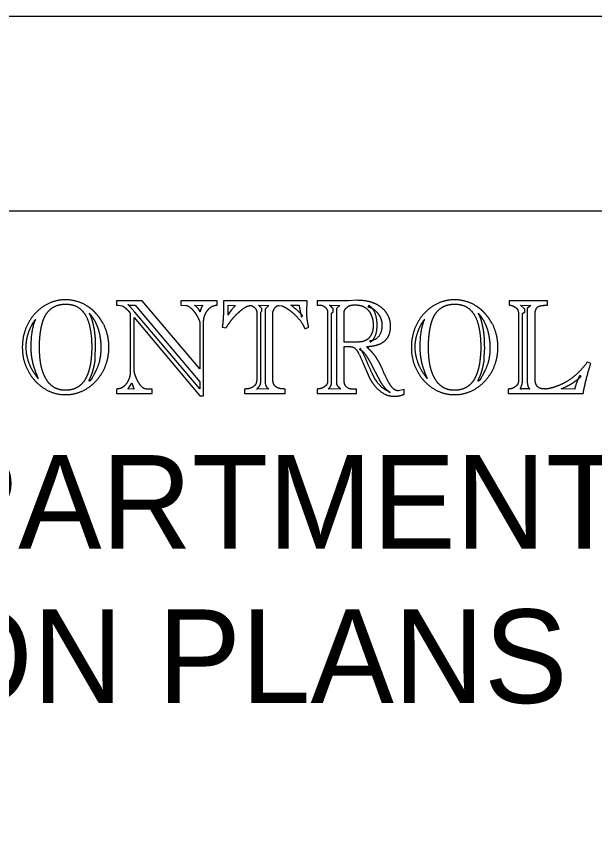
# Model space of a CAD drawing. Extents: x -0.96 to 2.36, y -0.12 to 0.92.
# Drawn here: x 0.6508 to 0.7127, y 0.8293 to 0.9167 of the extents above; entities that cross this region are included whole.
import ezdxf

# ---------------------------------------------------------------- set-up
doc = ezdxf.new("R2010")
doc.units = 0
for name, color, linetype in [('SHET_Border-Lines', 7, 'Continuous'), ('SHET_Border-Text', 7, 'Continuous'), ('SHET_Border-Text-Fully', 7, 'Continuous')]:
    doc.layers.add(name, color=color, linetype=linetype)

msp = doc.modelspace()

# ---------------------------------------------------------------- linework, layer by layer
at = {"layer": 'SHET_Border-Lines'}
for points in [[(0, 0), (1.416664, 0), (1.416664, 0.916665), (0, 0.916665)], [(0.041667, 0.020833), (1.395831, 0.020833), (1.395831, 0.895832), (0.041667, 0.895832)]]:
    msp.add_lwpolyline(points, close=True, dxfattribs=at)
at = {"layer": 'SHET_Border-Text-Fully'}
for p, q in [((0.656052, 0.886359), (0.656052, 0.886359)), ((0.697668, 0.886359), (0.697668, 0.886359)), ((0.654771, 0.885579), (0.654771, 0.885579)), ((0.662763, 0.885825), (0.662714, 0.885866)), ((0.662849, 0.885784), (0.663366, 0.885784)), ((0.669868, 0.88577), (0.670731, 0.885757)), ((0.678906, 0.885757), (0.679202, 0.885716)), ((0.680162, 0.885784), (0.681049, 0.885784)), ((0.687049, 0.885812), (0.687049, 0.885812)), ((0.688527, 0.88577), (0.688391, 0.88562)), ((0.696387, 0.885579), (0.696387, 0.885579)), ((0.658589, 0.884922), (0.658589, 0.884922)), ((0.66296, 0.884936), (0.662985, 0.878655)), ((0.670447, 0.885059), (0.670447, 0.885059)), ((0.676505, 0.885073), (0.676505, 0.877752)), ((0.678241, 0.877752), (0.678241, 0.884963)), ((0.681307, 0.884498), (0.681418, 0.884635)), ((0.684094, 0.885045), (0.684094, 0.877588)), ((0.700204, 0.884922), (0.700204, 0.884922)), ((0.704526, 0.884772), (0.704526, 0.87778)), ((0.704933, 0.87767), (0.704933, 0.884676)), ((0.706287, 0.877958), (0.706287, 0.884799)), ((0.672823, 0.883431), (0.673229, 0.883376)), ((0.681665, 0.883266), (0.682071, 0.883444)), ((0.688564, 0.881953), (0.688687, 0.88183)), ((0.659242, 0.880243), (0.659278, 0.881282)), ((0.687591, 0.881159), (0.687492, 0.88105)), ((0.700857, 0.880243), (0.700894, 0.881282)), ((0.687862, 0.879641), (0.688527, 0.878094)), ((0.71226, 0.879545), (0.711878, 0.879709)), ((0.711213, 0.878176), (0.711078, 0.878313)), ((0.653121, 0.877958), (0.653121, 0.877958)), ((0.662923, 0.877123), (0.663157, 0.877465)), ((0.694737, 0.877958), (0.694737, 0.877958)), ((0.676468, 0.876767), (0.676517, 0.876808)), ((0.677798, 0.876822), (0.676579, 0.876849)), ((0.705733, 0.876836), (0.704883, 0.876836))]:
    msp.add_line(p, q, dxfattribs=at)
for points in [[(0.67041, 0.883951), (0.67041, 0.878997), (0.664265, 0.886249), (0.661495, 0.886249), (0.661495, 0.885784), (0.661692, 0.885784), (0.66211, 0.885716)], [(0.672294, 0.885784), (0.672294, 0.886249), (0.668391, 0.886249), (0.668391, 0.885798), (0.66892, 0.885757)], [(0.681874, 0.885045), (0.681923, 0.886249), (0.672971, 0.886249)], [(0.687221, 0.886304), (0.68631, 0.886249), (0.682985, 0.886249), (0.682985, 0.885784), (0.683367, 0.885784)], [(0.707629, 0.885784), (0.707629, 0.886249), (0.703516, 0.886249), (0.703516, 0.885812)], [(0.663539, 0.885743), (0.663859, 0.885374), (0.67041, 0.877588), (0.67041, 0.876836), (0.663477, 0.885032), (0.662935, 0.885661)], [(0.676948, 0.877643), (0.676948, 0.885032), (0.677071, 0.885141), (0.677071, 0.885428), (0.676763, 0.885716), (0.676702, 0.885784), (0.677822, 0.885757), (0.677416, 0.885346), (0.677416, 0.877588)], [(0.684352, 0.885757), (0.684291, 0.885812), (0.684327, 0.885784), (0.685411, 0.885757), (0.685029, 0.885428), (0.685029, 0.877479)], [(0.6845, 0.877424), (0.6845, 0.884936), (0.684697, 0.885073), (0.684697, 0.885387)], [(0.705204, 0.885032), (0.705204, 0.885374), (0.704736, 0.885784), (0.705832, 0.885757), (0.705438, 0.885428), (0.705438, 0.87778)], [(0.663391, 0.878847), (0.663391, 0.884484), (0.670435, 0.87611), (0.670829, 0.87611), (0.670829, 0.884033)], [(0.68732, 0.881844), (0.685879, 0.881844), (0.685879, 0.884908), (0.685854, 0.884936)], [(0.685879, 0.877561), (0.685879, 0.881351), (0.686519, 0.881351)], [(0.688748, 0.87949), (0.689179, 0.878642), (0.689758, 0.877574)], [(0.661495, 0.876822), (0.661495, 0.876329), (0.665324, 0.876329), (0.665324, 0.876795), (0.664696, 0.876822)], [(0.663391, 0.876822), (0.662775, 0.876836), (0.662763, 0.876822)], [(0.675212, 0.876822), (0.675212, 0.876329), (0.679547, 0.876329), (0.679547, 0.876822)], [(0.682961, 0.876822), (0.682961, 0.876329), (0.687172, 0.876357), (0.687172, 0.876822), (0.686618, 0.876822)], [(0.685251, 0.877041), (0.68546, 0.876822), (0.684167, 0.876849), (0.684266, 0.876918)], [(0.692295, 0.876261), (0.692295, 0.876767), (0.691679, 0.87663)], [(0.703418, 0.876822), (0.703418, 0.876329), (0.711435, 0.876329)], [(0.710523, 0.876822), (0.709083, 0.876836), (0.709538, 0.877041)]]:
    msp.add_lwpolyline(points, dxfattribs=at)
msp.add_lwpolyline([(0.673438, 0.885784), (0.674214, 0.885757), (0.674079, 0.885606), (0.673783, 0.885264), (0.673537, 0.884895), (0.673438, 0.88473)], close=True, dxfattribs=at)
for points in [[(0.656052, 0.886359), (0.654784, 0.886359), (0.653725, 0.885675)], [(0.65838, 0.885688), (0.657296, 0.886359), (0.656052, 0.886359)], [(0.672971, 0.886249), (0.672971, 0.884293), (0.672823, 0.883431)], [(0.689222, 0.885921), (0.688416, 0.886304), (0.687221, 0.886304)], [(0.697668, 0.886359), (0.696399, 0.886359), (0.69534, 0.885675)], [(0.699995, 0.885688), (0.698911, 0.886359), (0.697668, 0.886359)], [(0.653725, 0.885675), (0.652666, 0.884991), (0.65205, 0.883828)], [(0.653922, 0.884717), (0.65423, 0.885264), (0.654771, 0.885579)], [(0.654771, 0.885579), (0.655326, 0.885894), (0.656077, 0.885894)], [(0.656077, 0.885894), (0.657099, 0.885894), (0.657708, 0.885326)], [(0.657708, 0.885326), (0.658318, 0.884758), (0.658589, 0.883718)], [(0.659322, 0.884888), (0.658897, 0.88536), (0.65838, 0.885688)], [(0.66211, 0.885716), (0.662221, 0.885688), (0.662406, 0.885524)], [(0.662406, 0.885524), (0.662578, 0.885401), (0.662646, 0.885326)], [(0.662646, 0.885326), (0.662714, 0.88525), (0.662812, 0.885155)], [(0.662714, 0.885866), (0.662726, 0.885866), (0.662849, 0.885784)], [(0.662935, 0.885661), (0.662886, 0.885716), (0.662763, 0.885825)], [(0.663366, 0.885784), (0.663502, 0.885784), (0.663539, 0.885743)], [(0.66892, 0.885757), (0.669191, 0.885757), (0.669548, 0.885401)], [(0.669548, 0.885401), (0.669905, 0.885045), (0.670158, 0.88458)], [(0.670447, 0.885059), (0.670312, 0.885456), (0.669868, 0.88577)], [(0.670731, 0.885757), (0.670521, 0.885483), (0.670447, 0.885059)], [(0.67102, 0.884847), (0.671211, 0.885264), (0.671531, 0.885524)], [(0.671531, 0.885524), (0.671851, 0.885784), (0.672294, 0.885784)], [(0.674565, 0.885004), (0.674793, 0.885209), (0.675039, 0.885401)], [(0.675039, 0.885401), (0.675544, 0.885757), (0.675889, 0.885757)], [(0.675889, 0.885757), (0.675914, 0.885743), (0.675957, 0.885736)], [(0.675957, 0.885736), (0.676, 0.885729), (0.676086, 0.885661)], [(0.676086, 0.885661), (0.676259, 0.885579), (0.676382, 0.885415)], [(0.676382, 0.885415), (0.676505, 0.88525), (0.676505, 0.885073)], [(0.678241, 0.884963), (0.678241, 0.885209), (0.678444, 0.885483)], [(0.678444, 0.885483), (0.678647, 0.885757), (0.678906, 0.885757)], [(0.679202, 0.885716), (0.679522, 0.885593), (0.679873, 0.885353)], [(0.679873, 0.885353), (0.680224, 0.885114), (0.680605, 0.884744)], [(0.680729, 0.885333), (0.680285, 0.885702), (0.680162, 0.885784)], [(0.681418, 0.884635), (0.681172, 0.884963), (0.680729, 0.885333)], [(0.681049, 0.885784), (0.681049, 0.885702), (0.68116, 0.885168)], [(0.68116, 0.885168), (0.681197, 0.884963), (0.681307, 0.884498)], [(0.683367, 0.885784), (0.683589, 0.885784), (0.683841, 0.885551)], [(0.683841, 0.885551), (0.684094, 0.885319), (0.684094, 0.885045)], [(0.684697, 0.885387), (0.684549, 0.885551), (0.684352, 0.885757)], [(0.685854, 0.884936), (0.685854, 0.885305), (0.686162, 0.885551)], [(0.686162, 0.885551), (0.686335, 0.885702), (0.686519, 0.885757)], [(0.686519, 0.885757), (0.686704, 0.885812), (0.687049, 0.885812)], [(0.687049, 0.885812), (0.687714, 0.885812), (0.688126, 0.885524)], [(0.688126, 0.885524), (0.688539, 0.885237), (0.688755, 0.884737)], [(0.688391, 0.88562), (0.68881, 0.885538), (0.689142, 0.885237)], [(0.689389, 0.88365), (0.689389, 0.885114), (0.688527, 0.88577)], [(0.689142, 0.885237), (0.689487, 0.884963), (0.689709, 0.884525)], [(0.690429, 0.884902), (0.690029, 0.885538), (0.689222, 0.885921)], [(0.69534, 0.885675), (0.694281, 0.884991), (0.693665, 0.883828)], [(0.695537, 0.884717), (0.695845, 0.885264), (0.696387, 0.885579)], [(0.696387, 0.885579), (0.696941, 0.885894), (0.697692, 0.885894)], [(0.697692, 0.885894), (0.698714, 0.885894), (0.699324, 0.885326)], [(0.699324, 0.885326), (0.699933, 0.884758), (0.700204, 0.883718)], [(0.700937, 0.884888), (0.700512, 0.88536), (0.699995, 0.885688)], [(0.703516, 0.885812), (0.704058, 0.885702), (0.704292, 0.885469)], [(0.704292, 0.885469), (0.704526, 0.885237), (0.704526, 0.884772)], [(0.706287, 0.884799), (0.706287, 0.885442), (0.706644, 0.885647)], [(0.706644, 0.885647), (0.706903, 0.885784), (0.707629, 0.885784)], [(0.652111, 0.882883), (0.652382, 0.883663), (0.652863, 0.884306)], [(0.652863, 0.884306), (0.652345, 0.883253), (0.652345, 0.88131)], [(0.653645, 0.884101), (0.653762, 0.884443), (0.653922, 0.884717)], [(0.658589, 0.884922), (0.658613, 0.884895), (0.65865, 0.884854)], [(0.658983, 0.883923), (0.658847, 0.884498), (0.658589, 0.884922)], [(0.65865, 0.884854), (0.659032, 0.884416), (0.659309, 0.883841)], [(0.660067, 0.883841), (0.659746, 0.884416), (0.659322, 0.884888)], [(0.662812, 0.885155), (0.66296, 0.884963), (0.66296, 0.884936)], [(0.670158, 0.88458), (0.67041, 0.884115), (0.67041, 0.883951)], [(0.670829, 0.884033), (0.670829, 0.884429), (0.67102, 0.884847)], [(0.673229, 0.883376), (0.673586, 0.883964), (0.674054, 0.884484)], [(0.674054, 0.884484), (0.674337, 0.884799), (0.674565, 0.885004)], [(0.680605, 0.884744), (0.68132, 0.884087), (0.681665, 0.883266)], [(0.681917, 0.884211), (0.681874, 0.884553), (0.681874, 0.885045)], [(0.688755, 0.884737), (0.68897, 0.884238), (0.68897, 0.883622)], [(0.689709, 0.884525), (0.689906, 0.884101), (0.689906, 0.883677)], [(0.690829, 0.883581), (0.690829, 0.884265), (0.690429, 0.884902)], [(0.693727, 0.882883), (0.693998, 0.883663), (0.694478, 0.884306)], [(0.694478, 0.884306), (0.693961, 0.883253), (0.693961, 0.88131)], [(0.69526, 0.884101), (0.695377, 0.884443), (0.695537, 0.884717)], [(0.700204, 0.884922), (0.700229, 0.884895), (0.700266, 0.884854)], [(0.700598, 0.883923), (0.700463, 0.884498), (0.700204, 0.884922)], [(0.700266, 0.884854), (0.700648, 0.884416), (0.700925, 0.883841)], [(0.701682, 0.883841), (0.701362, 0.884416), (0.700937, 0.884888)], [(0.704933, 0.884676), (0.704933, 0.884867), (0.704957, 0.884908)], [(0.704957, 0.884908), (0.704982, 0.884949), (0.705204, 0.885032)], [(0.65205, 0.883828), (0.651434, 0.882664), (0.651434, 0.881282)], [(0.653441, 0.883301), (0.653528, 0.883759), (0.653645, 0.884101)], [(0.658589, 0.883718), (0.65886, 0.882678), (0.65886, 0.88131)], [(0.659205, 0.882726), (0.659131, 0.883335), (0.658983, 0.883923)], [(0.659309, 0.883841), (0.659586, 0.883266), (0.65971, 0.882596)], [(0.660695, 0.881282), (0.660695, 0.882692), (0.660067, 0.883841)], [(0.682071, 0.883444), (0.68196, 0.883869), (0.681917, 0.884211)], [(0.689906, 0.883677), (0.689906, 0.882103), (0.688564, 0.881953)], [(0.688687, 0.88183), (0.689389, 0.882377), (0.689389, 0.88365)], [(0.68897, 0.883622), (0.68897, 0.883198), (0.688859, 0.882877)], [(0.690442, 0.88222), (0.690829, 0.882733), (0.690829, 0.883581)], [(0.693665, 0.883828), (0.69305, 0.882664), (0.69305, 0.881282)], [(0.695057, 0.883301), (0.695143, 0.883759), (0.69526, 0.884101)], [(0.700204, 0.883718), (0.700475, 0.882678), (0.700475, 0.88131)], [(0.70082, 0.882726), (0.700746, 0.883335), (0.700598, 0.883923)], [(0.700925, 0.883841), (0.701202, 0.883266), (0.701325, 0.882596)], [(0.70231, 0.881282), (0.70231, 0.882692), (0.701682, 0.883841)], [(0.651841, 0.881282), (0.651841, 0.88209), (0.652111, 0.882883)], [(0.653312, 0.88235), (0.653355, 0.882842), (0.653441, 0.883301)], [(0.659278, 0.881282), (0.659278, 0.882117), (0.659205, 0.882726)], [(0.65971, 0.882596), (0.659771, 0.882254), (0.659808, 0.881912)], [(0.688859, 0.882877), (0.688748, 0.882555), (0.688539, 0.882309)], [(0.693456, 0.881282), (0.693456, 0.88209), (0.693727, 0.882883)], [(0.694928, 0.88235), (0.694971, 0.882842), (0.695057, 0.883301)], [(0.700894, 0.881282), (0.700894, 0.882117), (0.70082, 0.882726)], [(0.701325, 0.882596), (0.701387, 0.882254), (0.701423, 0.881912)], [(0.653269, 0.881282), (0.653269, 0.881857), (0.653312, 0.88235)], [(0.659808, 0.881912), (0.659845, 0.88157), (0.659845, 0.881282)], [(0.688539, 0.882309), (0.688145, 0.881844), (0.68732, 0.881844)], [(0.689327, 0.881515), (0.690054, 0.881707), (0.690442, 0.88222)], [(0.694884, 0.881282), (0.694884, 0.881857), (0.694928, 0.88235)], [(0.701423, 0.881912), (0.70146, 0.88157), (0.70146, 0.881282)], [(0.651434, 0.881282), (0.651434, 0.879901), (0.65205, 0.878751)], [(0.652111, 0.879736), (0.651841, 0.880544), (0.651841, 0.881282)], [(0.652345, 0.88131), (0.652345, 0.880667), (0.652444, 0.880078)], [(0.653417, 0.879456), (0.653269, 0.88027), (0.653269, 0.881282)], [(0.65886, 0.88131), (0.65886, 0.880393), (0.658712, 0.879449)], [(0.659845, 0.881282), (0.659845, 0.879873), (0.659334, 0.878847)], [(0.660073, 0.878744), (0.660695, 0.879901), (0.660695, 0.881282)], [(0.686519, 0.881351), (0.686913, 0.881351), (0.687184, 0.880995)], [(0.687184, 0.880995), (0.687455, 0.880639), (0.687862, 0.879641)], [(0.687492, 0.88105), (0.687652, 0.881023), (0.687886, 0.88079)], [(0.688324, 0.879682), (0.687862, 0.880749), (0.687591, 0.881159)], [(0.688293, 0.881337), (0.688293, 0.881351), (0.688527, 0.881378)], [(0.68849, 0.881324), (0.688293, 0.881324), (0.688293, 0.881337)], [(0.688317, 0.881324), (0.688317, 0.881351), (0.688367, 0.881351)], [(0.688564, 0.881036), (0.688317, 0.881255), (0.688317, 0.881324)], [(0.688367, 0.881351), (0.688403, 0.881351), (0.68849, 0.881324)], [(0.688527, 0.881378), (0.68897, 0.881433), (0.689327, 0.881515)], [(0.689352, 0.880078), (0.689007, 0.880639), (0.688564, 0.881036)], [(0.69305, 0.881282), (0.69305, 0.879901), (0.693665, 0.878751)], [(0.693727, 0.879736), (0.693456, 0.880544), (0.693456, 0.881282)], [(0.693961, 0.88131), (0.693961, 0.880667), (0.694059, 0.880078)], [(0.695032, 0.879456), (0.694884, 0.88027), (0.694884, 0.881282)], [(0.700475, 0.88131), (0.700475, 0.880393), (0.700327, 0.879449)], [(0.70146, 0.881282), (0.70146, 0.879873), (0.700949, 0.878847)], [(0.701688, 0.878744), (0.70231, 0.879901), (0.70231, 0.881282)], [(0.652444, 0.880078), (0.652543, 0.87949), (0.65274, 0.878943)], [(0.659223, 0.879866), (0.659242, 0.880037), (0.659242, 0.880243)], [(0.687886, 0.88079), (0.68812, 0.880557), (0.688317, 0.880243)], [(0.688317, 0.880243), (0.688403, 0.880106), (0.688545, 0.879859)], [(0.690041, 0.878738), (0.689721, 0.879517), (0.689352, 0.880078)], [(0.694059, 0.880078), (0.694158, 0.87949), (0.694355, 0.878943)], [(0.700838, 0.879866), (0.700857, 0.880037), (0.700857, 0.880243)], [(0.6529, 0.878259), (0.652382, 0.878929), (0.652111, 0.879736)], [(0.653916, 0.877999), (0.653565, 0.878642), (0.653417, 0.879456)], [(0.658712, 0.879449), (0.658613, 0.878984), (0.658509, 0.878649)], [(0.658687, 0.877985), (0.658946, 0.878532), (0.659075, 0.879114)], [(0.659075, 0.879114), (0.659205, 0.879695), (0.659223, 0.879866)], [(0.689081, 0.878047), (0.688785, 0.878614), (0.688324, 0.879682)], [(0.688545, 0.879859), (0.688687, 0.879613), (0.688748, 0.87949)], [(0.694515, 0.878259), (0.693998, 0.878929), (0.693727, 0.879736)], [(0.695531, 0.877999), (0.69518, 0.878642), (0.695032, 0.879456)], [(0.700327, 0.879449), (0.700229, 0.878984), (0.700124, 0.878649)], [(0.700303, 0.877985), (0.700561, 0.878532), (0.700691, 0.879114)], [(0.700691, 0.879114), (0.70082, 0.879695), (0.700838, 0.879866)], [(0.711878, 0.879709), (0.711201, 0.878765), (0.710425, 0.878149)], [(0.711435, 0.876329), (0.711693, 0.877862), (0.71226, 0.879545)], [(0.65205, 0.878751), (0.652666, 0.877602), (0.653731, 0.876911)], [(0.65274, 0.878943), (0.652961, 0.8783), (0.653121, 0.877958)], [(0.653121, 0.877958), (0.653035, 0.878081), (0.6529, 0.878259)], [(0.658509, 0.878649), (0.658404, 0.878313), (0.658232, 0.877999)], [(0.658386, 0.876904), (0.659451, 0.877588), (0.660073, 0.878744)], [(0.659334, 0.878847), (0.658823, 0.877821), (0.658798, 0.877821)], [(0.662985, 0.878655), (0.662985, 0.878231), (0.6628, 0.877807)], [(0.663594, 0.878074), (0.663391, 0.878587), (0.663391, 0.878847)], [(0.690891, 0.877123), (0.690522, 0.877602), (0.690041, 0.878738)], [(0.693665, 0.878751), (0.694281, 0.877602), (0.695346, 0.876911)], [(0.694355, 0.878943), (0.694577, 0.8783), (0.694737, 0.877958)], [(0.694737, 0.877958), (0.694651, 0.878081), (0.694515, 0.878259)], [(0.700124, 0.878649), (0.70002, 0.878313), (0.699847, 0.877999)], [(0.700001, 0.876904), (0.701066, 0.877588), (0.701688, 0.878744)], [(0.700949, 0.878847), (0.700438, 0.877821), (0.700414, 0.877821)], [(0.710425, 0.877547), (0.710905, 0.877876), (0.711213, 0.878176)], [(0.711078, 0.878313), (0.710745, 0.87767), (0.710523, 0.876822)], [(0.654796, 0.87702), (0.654266, 0.877356), (0.653916, 0.877999)], [(0.658232, 0.877999), (0.657936, 0.877383), (0.65737, 0.877034)], [(0.658577, 0.877684), (0.658577, 0.877752), (0.658687, 0.877985)], [(0.658589, 0.877657), (0.658577, 0.877657), (0.658577, 0.877684)], [(0.658798, 0.877821), (0.658638, 0.877657), (0.658589, 0.877657)], [(0.6628, 0.877807), (0.662615, 0.877383), (0.662295, 0.877109)], [(0.663157, 0.877465), (0.663231, 0.877178), (0.663391, 0.876822)], [(0.664099, 0.877191), (0.663797, 0.877561), (0.663594, 0.878074)], [(0.676505, 0.877752), (0.676505, 0.877342), (0.67616, 0.877082)], [(0.676739, 0.877041), (0.676948, 0.877301), (0.676948, 0.877643)], [(0.677416, 0.877588), (0.677416, 0.877068), (0.677798, 0.876822)], [(0.678531, 0.877089), (0.678241, 0.877356), (0.678241, 0.877752)], [(0.684094, 0.877588), (0.684094, 0.877301), (0.683749, 0.877061)], [(0.684266, 0.876918), (0.6845, 0.877164), (0.6845, 0.877424)], [(0.685029, 0.877479), (0.685029, 0.877273), (0.685251, 0.877041)], [(0.686113, 0.877055), (0.685879, 0.87726), (0.685879, 0.877561)], [(0.688527, 0.878094), (0.688785, 0.877574), (0.689278, 0.876986)], [(0.689906, 0.877), (0.689376, 0.877479), (0.689081, 0.878047)], [(0.689758, 0.877574), (0.689832, 0.877438), (0.689986, 0.877226)], [(0.696411, 0.87702), (0.695882, 0.877356), (0.695531, 0.877999)], [(0.699847, 0.877999), (0.699552, 0.877383), (0.698985, 0.877034)], [(0.700192, 0.877684), (0.700192, 0.877752), (0.700303, 0.877985)], [(0.700204, 0.877657), (0.700192, 0.877657), (0.700192, 0.877684)], [(0.700414, 0.877821), (0.700254, 0.877657), (0.700204, 0.877657)], [(0.704526, 0.87778), (0.704526, 0.877342), (0.704218, 0.877109)], [(0.704773, 0.877013), (0.704933, 0.877314), (0.704933, 0.87767)], [(0.705438, 0.87778), (0.705438, 0.877), (0.705733, 0.876836)], [(0.706404, 0.877287), (0.706287, 0.877533), (0.706287, 0.877958)], [(0.710425, 0.878149), (0.709649, 0.877533), (0.708855, 0.877212)], [(0.709538, 0.877041), (0.709785, 0.877164), (0.710105, 0.877342)], [(0.710105, 0.877342), (0.710166, 0.877383), (0.710425, 0.877547)], [(0.653731, 0.876911), (0.654796, 0.87622), (0.656052, 0.87622)], [(0.656052, 0.876685), (0.655326, 0.876685), (0.654796, 0.87702)], [(0.65737, 0.877034), (0.656803, 0.876685), (0.656052, 0.876685)], [(0.656052, 0.87622), (0.65732, 0.87622), (0.658386, 0.876904)], [(0.662295, 0.877109), (0.662, 0.876822), (0.661495, 0.876822)], [(0.662751, 0.876836), (0.662751, 0.876877), (0.662923, 0.877123)], [(0.662763, 0.876822), (0.662751, 0.876822), (0.662751, 0.876836)], [(0.664696, 0.876822), (0.664401, 0.876822), (0.664099, 0.877191)], [(0.67616, 0.877082), (0.675815, 0.876822), (0.675212, 0.876822)], [(0.676579, 0.876849), (0.67648, 0.876767), (0.676468, 0.876767)], [(0.676517, 0.876808), (0.67664, 0.876918), (0.676739, 0.877041)], [(0.679547, 0.876822), (0.67882, 0.876822), (0.678531, 0.877089)], [(0.683749, 0.877061), (0.683404, 0.876822), (0.682961, 0.876822)], [(0.686618, 0.876822), (0.686322, 0.876822), (0.686113, 0.877055)], [(0.689278, 0.876986), (0.690189, 0.876042), (0.691211, 0.876042)], [(0.690485, 0.87663), (0.690164, 0.876767), (0.689906, 0.877)], [(0.689986, 0.877226), (0.69014, 0.877013), (0.690306, 0.876842)], [(0.690306, 0.876842), (0.690472, 0.876671), (0.690669, 0.876521)], [(0.690706, 0.876507), (0.690706, 0.876535), (0.690485, 0.87663)], [(0.690669, 0.876521), (0.690768, 0.876452), (0.690768, 0.876439)], [(0.690669, 0.876493), (0.690706, 0.876493), (0.690706, 0.876507)], [(0.690768, 0.876439), (0.690756, 0.876439), (0.690669, 0.876493)], [(0.691679, 0.87663), (0.691236, 0.87663), (0.690891, 0.877123)], [(0.695346, 0.876911), (0.696411, 0.87622), (0.697668, 0.87622)], [(0.697668, 0.876685), (0.696941, 0.876685), (0.696411, 0.87702)], [(0.698985, 0.877034), (0.698419, 0.876685), (0.697668, 0.876685)], [(0.697668, 0.87622), (0.698936, 0.87622), (0.700001, 0.876904)], [(0.703867, 0.87689), (0.703713, 0.876822), (0.703418, 0.876822)], [(0.704218, 0.877109), (0.704021, 0.876959), (0.703867, 0.87689)], [(0.704711, 0.876849), (0.704711, 0.876904), (0.704773, 0.877013)], [(0.70476, 0.876795), (0.704711, 0.876795), (0.704711, 0.876849)], [(0.704883, 0.876836), (0.704797, 0.876795), (0.70476, 0.876795)], [(0.706767, 0.876918), (0.706521, 0.877041), (0.706404, 0.877287)], [(0.707457, 0.876822), (0.707038, 0.876822), (0.706767, 0.876918)], [(0.708855, 0.877212), (0.708061, 0.87689), (0.707457, 0.876822)], [(0.691211, 0.876042), (0.691716, 0.876042), (0.692295, 0.876261)]]:
    msp.add_open_spline(points, degree=2, dxfattribs=at)

# ---------------------------------------------------------------- texts
at = {"layer": 'SHET_Border-Text'}
for s, p in [('ARKANSAS DEPARTMENT OF TRANSPORTATION', (0.54695, 0.859755)), ('CONSTRUCTION PLANS FOR STATE HIGHWAY', (0.554475, 0.843255))]:
    msp.add_text(s, height=0.01, dxfattribs=at).set_placement(p)

doc.saveas('drawing.dxf')
